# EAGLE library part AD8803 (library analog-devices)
ANALOG DEVICES
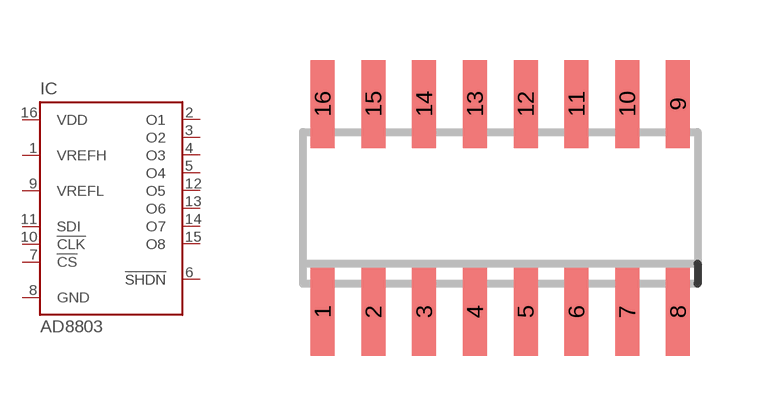
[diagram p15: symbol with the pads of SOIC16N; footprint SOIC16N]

Designator prefix IC

## AD8803 (OC_FARNELL: unknown; OC_NEWARK: unknown)  [SOIC16N]
1  VREFH  in
2  O1  out
3  O2  out
4  O3  out
5  O4  out
6  !SHDN  in
7  !CS  in
8  GND  pwr
9  VREFL  in
10  !CLK  in
11  SDI  in
12  O5  out
13  O6  out
14  O7  out
15  O8  out
16  VDD  pwr

## Footprint SOIC16N (pad centres in mm)
SMALL OUTLINE INTEGRATED CIRCUIT
smd 0.6 x 2.2: 1 -4.445,-2.6; 2 -3.175,-2.6; 3 -1.905,-2.6; 4 -0.635,-2.6; 5 0.635,-2.6; 6 1.905,-2.6; 7 3.175,-2.6; 8 4.445,-2.6; 9 4.445,2.6; 10 3.175,2.6; 11 1.905,2.6; 12 0.635,2.6; 13 -0.635,2.6; 14 -1.905,2.6; 15 -3.175,2.6; 16 -4.445,2.6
